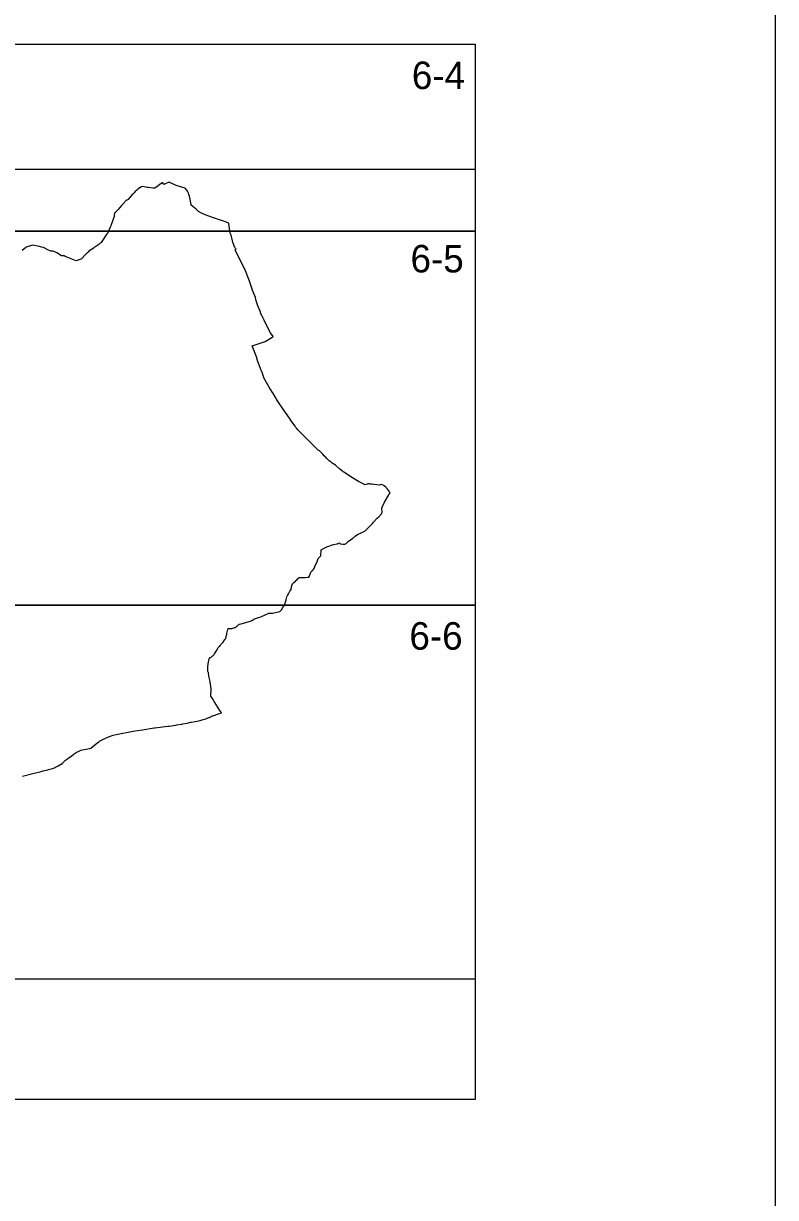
# Model space of a CAD drawing. Extents: x -449577 to -436680, y -1132317 to -1125726.
# Drawn here: x -439418.1 to -439166.8, y -1130335.5 to -1129943.1 of the extents above; entities that cross this region are included whole.
import ezdxf

# ---------------------------------------------------------------- set-up
doc = ezdxf.new("R2010")
doc.units = 0
for name, color, linetype in [('Vrstva 1', 7, 'Continuous'), ('Vrstva 10', 7, 'Continuous'), ('Vrstva 4', 7, 'Continuous')]:
    doc.layers.add(name, color=color, linetype=linetype)

msp = doc.modelspace()

# ---------------------------------------------------------------- linework, layer by layer
at = {"layer": 'Vrstva 1'}
msp.add_lwpolyline([(-440651.81, -1129648.53), (-440651.81, -1130698.53), (-439166.81, -1130698.53), (-439166.81, -1129648.53)], close=True, dxfattribs=at)
msp.add_lwpolyline([(-439418.52, -1130194.65), (-439414.98, -1130193.78), (-439412.21, -1130193.11), (-439411.54, -1130192.9), (-439410.05, -1130192.54), (-439409.84, -1130192.48), (-439408.41, -1130192.09), (-439407.81, -1130191.83), (-439407.59, -1130191.73), (-439407.43, -1130191.67), (-439406.61, -1130191.22), (-439406.55, -1130191.18), (-439405.24, -1130190.4), (-439404.09, -1130189.35), (-439403.44, -1130188.85), (-439403.31, -1130188.74), (-439403.29, -1130188.73), (-439403.13, -1130188.6), (-439402.98, -1130188.5), (-439402.18, -1130187.94), (-439402.12, -1130187.9), (-439402.05, -1130187.85), (-439401.54, -1130187.5), (-439401.17, -1130187.24), (-439400.51, -1130186.78), (-439399.92, -1130186.37), (-439399.76, -1130186.4), (-439399.75, -1130186.4), (-439399.73, -1130186.38), (-439399, -1130185.99), (-439396.04, -1130185.41), (-439395.62, -1130185.26), (-439393.59, -1130183.63), (-439393.12, -1130183.29), (-439393.09, -1130183.27), (-439392.73, -1130183.01), (-439392.55, -1130182.89), (-439391.16, -1130182.19), (-439389.75, -1130181.55), (-439389.45, -1130181.4), (-439388.19, -1130180.94), (-439387.19, -1130180.69), (-439381.48, -1130179.63), (-439380.06, -1130179.37), (-439378.35, -1130179.12), (-439374.48, -1130178.55), (-439374.24, -1130178.52), (-439369.94, -1130178), (-439369.41, -1130177.94), (-439367.26, -1130177.58), (-439366.94, -1130177.53), (-439365.28, -1130177.26), (-439364.88, -1130177.19), (-439363.47, -1130176.9), (-439362.18, -1130176.63), (-439361.97, -1130176.59), (-439360.8, -1130176.36), (-439360.13, -1130176.23), (-439360.11, -1130176.23), (-439359.2, -1130176.02), (-439359.13, -1130176), (-439358.48, -1130175.84), (-439358.13, -1130175.73), (-439357.24, -1130175.44), (-439356.8, -1130175.29), (-439356.15, -1130175.05), (-439356.03, -1130175.01), (-439354.94, -1130174.52), (-439354.94, -1130174.52), (-439354.82, -1130174.48), (-439354.17, -1130174.25), (-439354.08, -1130174.22), (-439353.65, -1130174.06), (-439351.99, -1130173.48), (-439352.01, -1130173.43), (-439352.12, -1130173.26), (-439352.28, -1130173.03), (-439352.5, -1130172.71), (-439354.2, -1130170.07), (-439354.41, -1130169.72), (-439354.58, -1130169.45), (-439355.02, -1130168.74), (-439355.55, -1130167.89), (-439355.39, -1130165.53), (-439355.38, -1130165.44), (-439355.77, -1130163.14), (-439355.77, -1130163.12), (-439355.78, -1130163.1), (-439355.78, -1130163.1), (-439355.78, -1130163.07), (-439356.19, -1130161.24), (-439356.2, -1130161.05), (-439356.26, -1130160.25), (-439356.36, -1130159.97), (-439356.37, -1130159.95), (-439356.48, -1130159.73), (-439356.52, -1130159.65), (-439356.53, -1130159.27), (-439356.56, -1130158.57), (-439356.51, -1130158.08), (-439356.51, -1130158.06), (-439356.42, -1130157.2), (-439356.4, -1130157.09), (-439356.11, -1130155.45), (-439356.03, -1130155.37), (-439355.73, -1130155.03), (-439355.67, -1130154.96), (-439355.41, -1130154.84), (-439355.35, -1130154.78), (-439355.09, -1130154.58), (-439354.86, -1130154.4), (-439354.65, -1130154.24), (-439354.59, -1130154.2), (-439354.51, -1130154.07), (-439354.43, -1130153.95), (-439354.32, -1130153.78), (-439354.1, -1130153.45), (-439353.68, -1130152.8), (-439353.55, -1130152.55), (-439353.54, -1130152.54), (-439353.4, -1130152.25), (-439353.35, -1130152.16), (-439353.17, -1130151.83), (-439353.03, -1130151.68), (-439352.73, -1130151.37), (-439352.56, -1130151.19), (-439352.28, -1130150.84), (-439352.15, -1130150.67), (-439351.46, -1130149.82), (-439350.8, -1130149.01), (-439350.51, -1130148.65), (-439350.27, -1130147.48), (-439350.21, -1130147.25), (-439350.14, -1130146.97), (-439349.82, -1130145.66), (-439349.74, -1130145.38), (-439349.74, -1130145.35), (-439349.72, -1130145.3), (-439349.56, -1130145.29), (-439349.54, -1130145.29), (-439349.3, -1130145.29), (-439348.61, -1130145.27), (-439348.6, -1130145.27), (-439348.57, -1130145.27), (-439347.89, -1130145.09), (-439347.69, -1130145.03), (-439347.27, -1130144.92), (-439347.25, -1130144.91), (-439347.19, -1130144.85), (-439346.89, -1130144.57), (-439346.77, -1130144.49), (-439346.43, -1130144.23), (-439346.01, -1130143.91), (-439345.94, -1130143.89), (-439345.38, -1130143.73), (-439342.68, -1130142.97), (-439342.09, -1130142.7), (-439341.76, -1130142.54), (-439341.71, -1130142.52), (-439341.61, -1130142.47), (-439341.25, -1130142.29), (-439341.2, -1130142.27), (-439341.17, -1130142.25), (-439341.16, -1130142.25), (-439341.13, -1130142.23), (-439340.82, -1130142.08), (-439340.76, -1130142.04), (-439340.65, -1130141.99), (-439339.57, -1130141.66), (-439339.14, -1130141.48), (-439338.62, -1130141.26), (-439337.61, -1130140.85), (-439336.19, -1130140.22), (-439336.05, -1130140.21), (-439334.92, -1130140.16), (-439332.52, -1130139.6), (-439331.99, -1130139.2), (-439331.92, -1130139.08), (-439331.83, -1130138.9), (-439331.57, -1130138.39), (-439331.22, -1130137.96), (-439331.2, -1130137.93), (-439330.99, -1130137.64), (-439330.88, -1130137.48), (-439330.87, -1130137.47), (-439330.33, -1130135.69), (-439330.32, -1130135.66), (-439330.12, -1130134.71), (-439329.86, -1130134.25), (-439329.67, -1130133.92), (-439329.12, -1130132.8), (-439328.74, -1130132.29), (-439328.71, -1130132.16), (-439328.64, -1130131.86), (-439328.61, -1130131.72), (-439328.55, -1130131.47), (-439328.53, -1130131.37), (-439328.21, -1130130.36), (-439328.2, -1130130.35), (-439327.91, -1130130.07), (-439327.25, -1130129.44), (-439327.2, -1130129.39), (-439326.73, -1130128.91), (-439326.47, -1130128.65), (-439326.37, -1130128.54), (-439326, -1130128.22), (-439325.96, -1130128.22), (-439325.95, -1130128.22), (-439325.54, -1130128.21), (-439325.37, -1130128.22), (-439324.74, -1130128.24), (-439324.03, -1130128.24), (-439323.06, -1130128.15), (-439323.03, -1130128.15), (-439322.78, -1130128.12), (-439322.56, -1130127.76), (-439322.51, -1130127.63), (-439322.49, -1130127.58), (-439322.47, -1130127.52), (-439322.11, -1130126.5), (-439321.97, -1130126.33), (-439321.87, -1130126.22), (-439321.83, -1130126.18), (-439321.77, -1130126.1), (-439321.65, -1130125.97), (-439321.38, -1130125.65), (-439321.29, -1130125.55), (-439321.19, -1130125.43), (-439320.85, -1130125.04), (-439320.78, -1130124.65), (-439320.72, -1130124.34), (-439320.65, -1130124.21), (-439320.1, -1130123.29), (-439319.99, -1130122.9), (-439319.8, -1130122.2), (-439319.68, -1130121.91), (-439319.39, -1130121.64), (-439318.84, -1130121.13), (-439318.77, -1130121.07), (-439318.67, -1130118.96), (-439317.65, -1130118.47), (-439317.25, -1130118.26), (-439317, -1130118.13), (-439316.71, -1130117.97), (-439316.49, -1130117.89), (-439316.15, -1130117.76), (-439316.1, -1130117.75), (-439315.01, -1130117.34), (-439315, -1130117.34), (-439314.51, -1130117.28), (-439314.43, -1130117.26), (-439313.4, -1130117), (-439313.25, -1130116.96), (-439313.16, -1130116.93), (-439312.99, -1130116.88), (-439312.46, -1130116.71), (-439312.46, -1130116.71), (-439312.45, -1130116.72), (-439312.45, -1130116.72), (-439312.42, -1130116.78), (-439312.29, -1130117), (-439311.41, -1130117.1), (-439311.21, -1130117.12), (-439310.85, -1130117.16), (-439310.76, -1130117.12), (-439310.33, -1130116.94), (-439309.68, -1130116.23), (-439308.04, -1130115.07), (-439307.95, -1130115), (-439307.78, -1130114.89), (-439307.27, -1130114.47), (-439306.52, -1130113.87), (-439305.25, -1130113.3), (-439304.63, -1130113.03), (-439304.09, -1130112.79), (-439304.03, -1130112.76), (-439302.38, -1130111.09), (-439301.54, -1130110.2), (-439301.18, -1130109.82), (-439299.99, -1130108.46), (-439299.39, -1130108), (-439299.34, -1130107.96), (-439298.5, -1130106.95), (-439298.3, -1130106.38), (-439298.39, -1130105.05), (-439298.17, -1130104.56), (-439297.53, -1130103.11), (-439296.07, -1130100.63), (-439296.04, -1130100.58), (-439296.04, -1130100.58), (-439296.02, -1130100.55), (-439295.99, -1130100.51), (-439295.84, -1130100.32), (-439295.58, -1130099.98), (-439295.84, -1130099.68), (-439295.98, -1130099.46), (-439296.45, -1130098.72), (-439296.65, -1130098.53), (-439296.8, -1130098.37), (-439296.99, -1130098.17), (-439297.57, -1130097.6), (-439298.42, -1130097.13), (-439298.87, -1130097.31), (-439299.2, -1130097.43), (-439300.95, -1130097.16), (-439301.56, -1130097.07), (-439301.7, -1130097.06), (-439302.29, -1130097.04), (-439302.67, -1130096.99), (-439302.83, -1130096.96), (-439302.87, -1130096.96), (-439302.9, -1130096.95), (-439302.9, -1130096.95), (-439302.93, -1130096.96), (-439303.03, -1130096.99), (-439303.16, -1130097.02), (-439304.06, -1130097.26), (-439304.13, -1130097.23), (-439306.2, -1130096.19), (-439308.22, -1130094.91), (-439311.13, -1130093.09), (-439311.29, -1130092.95), (-439311.33, -1130092.92), (-439311.42, -1130092.84), (-439312.56, -1130091.91), (-439313.71, -1130090.86), (-439313.82, -1130090.76), (-439315.03, -1130090), (-439315.31, -1130089.77), (-439315.94, -1130089.27), (-439316.25, -1130089.03), (-439316.75, -1130088.5), (-439317.47, -1130087.74), (-439317.62, -1130087.58), (-439318.08, -1130087.09), (-439319.05, -1130086.06), (-439319.25, -1130085.95), (-439319.25, -1130085.95), (-439319.43, -1130085.86), (-439319.63, -1130085.76), (-439320.46, -1130084.93), (-439321.09, -1130084.3), (-439322.27, -1130083.13), (-439323.2, -1130082.19), (-439323.36, -1130082.04), (-439323.8, -1130081.59), (-439324.04, -1130081.35), (-439324.13, -1130081.26), (-439324.17, -1130081.22), (-439324.69, -1130080.7), (-439325.33, -1130080.05), (-439325.41, -1130079.97), (-439325.43, -1130079.95), (-439325.58, -1130079.8), (-439326.41, -1130078.96), (-439326.79, -1130078.46), (-439327.07, -1130078.09), (-439327.39, -1130077.66), (-439327.75, -1130077.18), (-439328.7, -1130075.92), (-439329.07, -1130075.38), (-439331.61, -1130071.64), (-439331.78, -1130071.38), (-439332.55, -1130070.19), (-439333.22, -1130069.18), (-439334.06, -1130067.85), (-439334.86, -1130066.58), (-439334.94, -1130066.45), (-439336.03, -1130064.6), (-439337.71, -1130061.75), (-439337.71, -1130061.74), (-439337.71, -1130061.74), (-439337.72, -1130061.74), (-439338.05, -1130060.76), (-439338.5, -1130059.46), (-439338.56, -1130059.26), (-439339.94, -1130055.75), (-439340.23, -1130054.5), (-439341.71, -1130050.82), (-439341.08, -1130050.62), (-439337.36, -1130049.38), (-439335.39, -1130048.16), (-439335.21, -1130048.05), (-439335.15, -1130048.01), (-439334.95, -1130047.89), (-439334.68, -1130047.72), (-439335.6, -1130046.53), (-439337.01, -1130043.75), (-439337.76, -1130042.28), (-439338.29, -1130041.12), (-439338.31, -1130041.08), (-439338.37, -1130040.95), (-439338.38, -1130040.92), (-439338.4, -1130040.89), (-439338.44, -1130040.8), (-439338.77, -1130040.07), (-439339.09, -1130039.28), (-439339.8, -1130037.51), (-439340.21, -1130036.47), (-439340.36, -1130035.84), (-439340.62, -1130034.71), (-439341.36, -1130032.82), (-439341.56, -1130032.22), (-439342.5, -1130029.59), (-439342.77, -1130028.87), (-439343.96, -1130025.78), (-439344.03, -1130025.6), (-439344.06, -1130025.52), (-439347.41, -1130018.71), (-439347.1, -1130018.57), (-439347.08, -1130018.56), (-439347.18, -1130018.39), (-439347.26, -1130018.29), (-439347.43, -1130018.06), (-439347.49, -1130017.98), (-439348.1, -1130016.5), (-439348.15, -1130016.21), (-439348.25, -1130015.75), (-439348.26, -1130015.69), (-439348.77, -1130013.85), (-439349.07, -1130013.22), (-439349.08, -1130013.14), (-439349.12, -1130012.78), (-439349.26, -1130011.69), (-439349.54, -1130009.85), (-439349.6, -1130009.83), (-439349.9, -1130009.73), (-439350.28, -1130009.47), (-439350.29, -1130009.47), (-439354.59, -1130008.06), (-439357.38, -1130007.08), (-439358.69, -1130006.46), (-439359.66, -1130005.9), (-439360.38, -1130005.12), (-439362.06, -1130003.85), (-439362.12, -1130003.55), (-439362.7, -1130000.85), (-439362.85, -1130000.31), (-439363.03, -1129999.8), (-439363.08, -1129999.64), (-439363.33, -1129999.12), (-439363.58, -1129998.81), (-439364.16, -1129998.12), (-439364.91, -1129997.91), (-439367.09, -1129997.25), (-439369.18, -1129996.29), (-439369.8, -1129996.29), (-439370.75, -1129996.66), (-439370.88, -1129996.75), (-439370.95, -1129996.8), (-439371.09, -1129996.9), (-439371.13, -1129996.93), (-439371.15, -1129996.91), (-439371.36, -1129996.66), (-439371.61, -1129996.38), (-439371.69, -1129996.28), (-439371.78, -1129996.32), (-439372.29, -1129996.71), (-439372.48, -1129996.86), (-439373.15, -1129997.38), (-439373.9, -1129997.94), (-439374.24, -1129998.16), (-439374.83, -1129998.12), (-439376.31, -1129997.97), (-439376.77, -1129997.88), (-439378.36, -1129997.56), (-439378.66, -1129997.67), (-439379.22, -1129998.02), (-439379.77, -1129998.34), (-439380.26, -1129998.8), (-439380.79, -1129999.29), (-439381.19, -1129999.68), (-439381.2, -1129999.69), (-439381.53, -1130000.03), (-439381.66, -1130000.17), (-439382.17, -1130000.72), (-439382.62, -1130001.27), (-439382.78, -1130001.46), (-439383.14, -1130001.89), (-439383.88, -1130002.22), (-439383.9, -1130002.22), (-439384.1, -1130002.47), (-439384.96, -1130003.49), (-439385.34, -1130003.94), (-439386.47, -1130005.3), (-439386.48, -1130005.31), (-439387.72, -1130006.48), (-439387.84, -1130007.32), (-439387.89, -1130007.69), (-439387.93, -1130007.79), (-439388.41, -1130009.14), (-439388.85, -1130010.38), (-439388.88, -1130010.46), (-439389.18, -1130011.15), (-439390.11, -1130013.33), (-439390.13, -1130013.34), (-439390.7, -1130014.02), (-439391, -1130014.37), (-439391, -1130014.38), (-439391.34, -1130014.92), (-439392.21, -1130016.31), (-439392.3, -1130016.45), (-439392.47, -1130016.58), (-439393, -1130016.97), (-439393.61, -1130017.42), (-439393.61, -1130017.42), (-439394.58, -1130018.05), (-439394.71, -1130018.14), (-439394.89, -1130018.26), (-439396.19, -1130019.12), (-439396.2, -1130019.13), (-439396.46, -1130019.39), (-439396.58, -1130019.51), (-439396.8, -1130019.74), (-439397.08, -1130020.02), (-439397.65, -1130020.59), (-439398.81, -1130021.75), (-439399.01, -1130021.83), (-439400.51, -1130022.4), (-439403.32, -1130021.28), (-439403.32, -1130021.29), (-439403.33, -1130021.31), (-439404.24, -1130020.93), (-439404.55, -1130020.8), (-439404.57, -1130020.8), (-439404.96, -1130020.8), (-439405.44, -1130020.8), (-439407, -1130019.81), (-439407.26, -1130019.68), (-439407.55, -1130019.52), (-439407.61, -1130019.49), (-439407.65, -1130019.47), (-439408.19, -1130019.24), (-439408.24, -1130019.24), (-439408.25, -1130019.24), (-439408.4, -1130019.23), (-439408.52, -1130019.22), (-439408.83, -1130019.2), (-439408.85, -1130019.2), (-439408.85, -1130019.2), (-439408.96, -1130019.16), (-439409.2, -1130019.06), (-439409.8, -1130018.81), (-439409.96, -1130018.74), (-439411.48, -1130018.01), (-439412.1, -1130017.83), (-439412.77, -1130017.63), (-439415.09, -1130017.2), (-439415.1, -1130017.2), (-439415.5, -1130017.31), (-439417.24, -1130017.89), (-439417.37, -1130018), (-439418.58, -1130018.96)], dxfattribs=at)
at = {"layer": 'Vrstva 10'}
msp.add_lwpolyline([(-439267.22, -1129991.79), (-439267.22, -1130302.77), (-439600.09, -1130302.77), (-439600.09, -1130137.47), (-439579.72, -1130137.47), (-439579.72, -1130012.47), (-439579.72, -1129991.79), (-439267.22, -1129991.79)], dxfattribs=at)
at = {"layer": 'Vrstva 4'}
msp.add_line((-439579.72, -1129949.97), (-439267.22, -1129949.97), dxfattribs=at)
msp.add_lwpolyline([(-439267.22, -1129949.97), (-439267.22, -1130012.47), (-439423.47, -1130012.47), (-439423.47, -1129949.97)], dxfattribs=at)
for points in [[(-439267.22, -1130012.47), (-439267.22, -1130137.47), (-439423.47, -1130137.47), (-439423.47, -1130012.47)], [(-439267.22, -1130137.47), (-439267.22, -1130262.47), (-439423.47, -1130262.47), (-439423.47, -1130137.47)]]:
    msp.add_lwpolyline(points, close=True, dxfattribs=at)

# ---------------------------------------------------------------- texts
at = {"layer": 'Vrstva 1'}
for s, p in [('6-4', (-439288.35, -1129965.02)), ('6-5', (-439288.8, -1130026.31)), ('6-6', (-439289.17, -1130152.38))]:
    msp.add_text(s, height=9.2, dxfattribs=at).set_placement(p)

doc.saveas('drawing.dxf')
